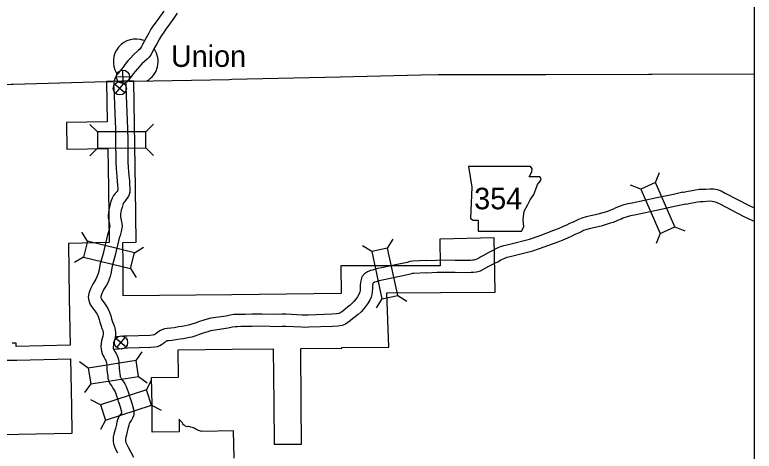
# Model space of a CAD drawing. Extents: x 1377389 to 1380723, y 1168351 to 1170484.
# Drawn here: x 1378097.6 to 1378279.2, y 1170112.1 to 1170219.2 of the extents above; entities that cross this region are included whole.
import ezdxf

# ---------------------------------------------------------------- set-up
doc = ezdxf.new("R2010")
doc.units = 0
doc.layers.add('B_Fill', color=7, linetype='Continuous')
doc.layers.add('B_Text', color=7, linetype='Continuous')

msp = doc.modelspace()

# ---------------------------------------------------------------- linework, layer by layer
at = {"layer": 'B_Fill'}
for p, q in [((1378124.19, 1170202.37), (1378124.12, 1170205.63)), ((1378122.53, 1170203.96), (1378125.78, 1170204.04)), ((1378122.16, 1170202.18), (1378124.65, 1170200.1)), ((1378122.36, 1170199.9), (1378124.45, 1170202.38)), ((1378117.9, 1170190.44), (1378116.03, 1170192.3)), ((1378129.78, 1170190.5), (1378131.64, 1170192.38)), ((1378117.93, 1170186.48), (1378116.07, 1170184.6)), ((1378129.81, 1170186.54), (1378131.68, 1170184.69)), ((1378254.91, 1170178), (1378255.87, 1170180.45)), ((1378251.28, 1170176.41), (1378248.82, 1170177.38)), ((1378259.67, 1170167.11), (1378262.12, 1170166.15)), ((1378115.43, 1170163.59), (1378114.06, 1170165.84)), ((1378256.04, 1170165.52), (1378255.07, 1170163.07)), ((1378185.24, 1170161.09), (1378183.02, 1170162.52)), ((1378189.11, 1170161.93), (1378190.54, 1170164.15)), ((1378126.97, 1170160.77), (1378129.23, 1170162.14)), ((1378114.49, 1170159.74), (1378112.23, 1170158.37)), ((1378126.03, 1170156.92), (1378127.4, 1170154.67)), ((1378191.63, 1170150.32), (1378193.85, 1170148.89)), ((1378187.76, 1170149.48), (1378186.33, 1170147.26)), ((1378122.45, 1170139.81), (1378124.94, 1170137.72)), ((1378122.65, 1170137.52), (1378124.74, 1170140.01)), ((1378127.37, 1170134.34), (1378128.92, 1170136.47)), ((1378115.63, 1170132.48), (1378113.5, 1170134.03)), ((1378127.99, 1170130.43), (1378130.12, 1170128.87)), ((1378116.25, 1170128.57), (1378114.7, 1170126.44)), ((1378129.94, 1170127.13), (1378131.15, 1170129.48)), ((1378118.64, 1170123.48), (1378116.29, 1170124.68)), ((1378131.16, 1170123.36), (1378133.51, 1170122.15)), ((1378119.85, 1170119.71), (1378118.65, 1170117.36))]:
    msp.add_line(p, q, dxfattribs=at)
for points in [[(1378134.21, 1170220.13), (1378133.13, 1170218.64), (1378132.29, 1170217.44), (1378131.53, 1170216.4), (1378131.05, 1170215.66), (1378130.54, 1170214.73), (1378129.86, 1170213.53), (1378129.38, 1170212.65), (1378128.99, 1170211.93), (1378128.72, 1170211.44), (1378128.46, 1170211), (1378128.27, 1170210.75), (1378128.01, 1170210.48), (1378126.68, 1170209.28), (1378126, 1170208.55), (1378125.36, 1170207.86), (1378124.74, 1170207.1), (1378124.36, 1170206.55), (1378123.87, 1170205.95), (1378123.4, 1170205.39), (1378123.08, 1170204.96), (1378122.87, 1170204.7), (1378122.67, 1170204.43), (1378122.49, 1170204.12), (1378122.38, 1170203.93), (1378122.21, 1170203.61), (1378122.07, 1170203.17), (1378121.96, 1170202.78), (1378121.94, 1170202.59)], [(1378137.51, 1170219.64), (1378136.66, 1170218.4), (1378135.58, 1170216.91), (1378134.73, 1170215.69), (1378134, 1170214.69), (1378133.63, 1170214.12), (1378133.16, 1170213.27), (1378132.48, 1170212.07), (1378132.02, 1170211.22), (1378131.62, 1170210.48), (1378131.31, 1170209.93), (1378130.97, 1170209.37), (1378130.58, 1170208.81), (1378130.08, 1170208.31), (1378128.78, 1170207.14), (1378128.2, 1170206.52), (1378127.63, 1170205.89), (1378127.13, 1170205.29), (1378126.76, 1170204.75), (1378126.18, 1170204.04), (1378125.75, 1170203.52), (1378125.47, 1170203.15), (1378125.26, 1170202.88), (1378125.16, 1170202.74), (1378125.09, 1170202.64), (1378125.09, 1170202.62)], [(1378125.72, 1170202.86), (1378126.88, 1170202.9), (1378150.29, 1170203.33), (1378150.89, 1170203.36), (1378177.46, 1170203.97), (1378197.29, 1170204.47)], [(1378197.29, 1170204.47), (1378201.57, 1170204.57), (1378227.75, 1170204.54), (1378227.98, 1170204.54), (1378253.31, 1170204.65), (1378254.09, 1170204.64), (1378279.16, 1170204.69)], [(1378012.99, 1170201.33), (1378018.47, 1170201.38), (1378044.97, 1170201.67), (1378045.21, 1170201.7), (1378070.3, 1170201.77), (1378070.43, 1170201.77), (1378096.77, 1170202.14), (1378097.18, 1170202.17), (1378120.12, 1170202.8), (1378121.69, 1170202.81)], [(1378124.12, 1170163.34), (1378127.44, 1170163.42), (1378127.27, 1170176.68), (1378126.83, 1170202.91), (1378123.92, 1170202.91), (1378120.13, 1170202.83), (1378120.3, 1170192.96), (1378110.28, 1170192.74), (1378110.4, 1170186.21)], [(1378122.09, 1170203.22), (1378122.07, 1170203.17), (1378121.96, 1170202.78), (1378121.9, 1170202.27), (1378121.86, 1170201.76), (1378121.89, 1170201.21), (1378122.31, 1170191.15)], [(1378124.95, 1170202.32), (1378124.94, 1170202.3), (1378124.91, 1170202.18), (1378124.89, 1170201.98), (1378124.87, 1170201.72), (1378124.88, 1170201.34), (1378125.31, 1170191.19)], [(1378122.31, 1170191.15), (1378122.35, 1170188.48), (1378122.38, 1170183.02), (1378122.49, 1170181.48), (1378122.63, 1170179.53), (1378122.75, 1170178.24), (1378122.81, 1170177.35), (1378122.87, 1170176.57), (1378122.89, 1170176.17), (1378122.88, 1170176.16), (1378122.86, 1170176.07), (1378122.83, 1170175.98), (1378122.8, 1170175.94), (1378122.58, 1170175.67), (1378122.25, 1170175.29), (1378121.88, 1170174.8), (1378121.51, 1170174.18), (1378121.23, 1170173.39), (1378121.05, 1170172.68), (1378120.85, 1170172.04), (1378120.66, 1170171.34), (1378120.58, 1170170.63), (1378120.54, 1170169.99), (1378120.57, 1170169.28), (1378120.68, 1170168.61), (1378120.78, 1170168.19), (1378120.84, 1170167.86), (1378120.9, 1170167.57), (1378120.93, 1170167.34), (1378120.81, 1170166.65), (1378120.62, 1170165.89), (1378120.38, 1170165.15), (1378119.28, 1170160.64), (1378118.74, 1170158.63)], [(1378125.31, 1170191.19), (1378125.35, 1170188.51), (1378125.38, 1170183.14), (1378125.48, 1170181.7), (1378125.62, 1170179.77), (1378125.74, 1170178.48), (1378125.8, 1170177.57), (1378125.86, 1170176.75), (1378125.89, 1170176.11), (1378125.85, 1170175.58), (1378125.7, 1170175.12), (1378125.53, 1170174.64), (1378125.23, 1170174.18), (1378124.89, 1170173.75), (1378124.59, 1170173.4), (1378124.36, 1170173.11), (1378124.24, 1170172.9), (1378124.1, 1170172.51), (1378123.94, 1170171.87), (1378123.74, 1170171.22), (1378123.62, 1170170.77), (1378123.57, 1170170.37), (1378123.55, 1170169.97), (1378123.56, 1170169.58), (1378123.62, 1170169.21), (1378123.72, 1170168.82), (1378123.8, 1170168.4), (1378123.86, 1170168.03), (1378123.96, 1170167.29), (1378123.75, 1170166.03), (1378123.5, 1170165.05), (1378123.26, 1170164.33), (1378122.18, 1170159.9), (1378121.63, 1170157.85)], [(1378110.4, 1170186.21), (1378120.42, 1170186.38), (1378120.6, 1170176.53), (1378120.77, 1170163.27), (1378110.77, 1170163.07), (1378110.96, 1170149.75), (1378111.21, 1170138.08), (1378097.98, 1170137.75)], [(1378261.6, 1170175.64), (1378259.35, 1170175.12), (1378255.28, 1170174.29)], [(1378261.6, 1170175.64), (1378261.77, 1170175.68), (1378262.92, 1170175.9), (1378263.92, 1170176.1), (1378264.77, 1170176.24), (1378265.64, 1170176.37), (1378266.54, 1170176.39), (1378267.28, 1170176.43), (1378268.26, 1170176.5), (1378269.23, 1170176.48), (1378270.08, 1170176.29), (1378271.02, 1170175.95), (1378272.05, 1170175.44), (1378277.95, 1170172.4), (1378279.16, 1170171.81)], [(1378255.23, 1170174.28), (1378249.19, 1170172.93), (1378248.19, 1170172.77), (1378247.11, 1170172.52), (1378245.72, 1170172.04), (1378244.85, 1170171.63)], [(1378262.4, 1170172.74), (1378263.5, 1170172.96), (1378264.45, 1170173.15), (1378265.23, 1170173.27), (1378265.91, 1170173.38), (1378266.65, 1170173.39), (1378267.45, 1170173.43), (1378268.34, 1170173.49), (1378268.87, 1170173.48), (1378269.25, 1170173.4), (1378269.85, 1170173.19), (1378270.69, 1170172.77), (1378276.61, 1170169.72), (1378278.73, 1170168.69), (1378279.16, 1170168.5)], [(1378198.58, 1170158.86), (1378201.17, 1170158.99), (1378202.14, 1170159.02), (1378205.73, 1170158.98), (1378208.55, 1170158.94), (1378209.53, 1170159), (1378210.04, 1170159.01), (1378210.38, 1170159.05), (1378210.87, 1170159.19), (1378211.26, 1170159.38), (1378211.81, 1170159.7), (1378212.62, 1170160.15), (1378213.33, 1170160.51), (1378214.11, 1170160.91), (1378214.9, 1170161.3), (1378215.49, 1170161.66), (1378216.1, 1170161.97), (1378216.88, 1170162.28), (1378217.68, 1170162.57), (1378218.84, 1170162.85), (1378223.98, 1170164.15), (1378226.58, 1170165.03), (1378229.97, 1170166.31), (1378231.13, 1170166.75), (1378232.18, 1170167.19), (1378233.19, 1170167.63), (1378233.91, 1170168.01), (1378234.78, 1170168.41), (1378235.41, 1170168.71), (1378236.06, 1170169.04), (1378236.92, 1170169.37), (1378237.95, 1170169.66), (1378238.98, 1170169.89), (1378240.18, 1170170.2), (1378241.21, 1170170.4), (1378242.03, 1170170.64), (1378242.97, 1170170.95), (1378243.61, 1170171.15), (1378244.4, 1170171.46), (1378244.85, 1170171.63)], [(1378262.4, 1170172.74), (1378260, 1170172.2), (1378255.88, 1170171.35)], [(1378255.89, 1170171.35), (1378249.76, 1170169.98), (1378248.77, 1170169.83), (1378247.94, 1170169.63), (1378246.91, 1170169.28), (1378246.88, 1170169.26)], [(1378198.74, 1170155.86), (1378201.28, 1170156), (1378202.17, 1170156.02), (1378205.7, 1170155.98), (1378208.62, 1170155.94), (1378209.67, 1170156), (1378210.26, 1170156.02), (1378210.96, 1170156.1), (1378211.94, 1170156.38), (1378212.67, 1170156.73), (1378213.29, 1170157.09), (1378214.02, 1170157.5), (1378214.69, 1170157.84), (1378215.46, 1170158.23), (1378216.34, 1170158.67), (1378216.95, 1170159.03), (1378217.35, 1170159.24), (1378217.94, 1170159.48), (1378218.54, 1170159.69), (1378219.57, 1170159.94), (1378224.83, 1170161.27), (1378227.59, 1170162.21), (1378231.04, 1170163.5), (1378232.24, 1170163.97), (1378233.36, 1170164.43), (1378234.48, 1170164.93), (1378235.22, 1170165.31), (1378236.06, 1170165.69), (1378236.74, 1170166.02), (1378237.28, 1170166.29), (1378237.87, 1170166.52), (1378238.69, 1170166.75), (1378239.68, 1170166.98), (1378240.84, 1170167.27), (1378241.91, 1170167.48), (1378242.92, 1170167.77), (1378243.89, 1170168.09), (1378244.61, 1170168.32), (1378245.5, 1170168.67), (1378246.88, 1170169.26), (1378246.54, 1170169.07)], [(1378202.15, 1170150.99), (1378215.57, 1170151.1), (1378215.27, 1170164.42), (1378201.96, 1170164.15), (1378202.06, 1170157.57)], [(1378124.23, 1170150.17), (1378124.2, 1170158.05), (1378124.12, 1170163.34)], [(1378118.74, 1170158.63), (1378118.61, 1170158.16), (1378118.22, 1170156.29), (1378118.09, 1170155.73), (1378117.95, 1170155.28), (1378117.77, 1170154.84), (1378117.5, 1170154.31), (1378117.23, 1170153.89), (1378116.88, 1170153.26), (1378116.53, 1170152.59), (1378116.22, 1170151.95), (1378115.98, 1170151.31), (1378115.8, 1170150.77), (1378115.66, 1170149.91), (1378115.82, 1170149.08), (1378116.07, 1170148.28), (1378116.48, 1170147.55), (1378116.89, 1170147.01), (1378117.27, 1170146.51), (1378117.58, 1170146.06), (1378117.81, 1170145.7), (1378118.05, 1170145.13), (1378118.29, 1170144.43), (1378118.48, 1170143.72), (1378118.78, 1170142.79), (1378119.01, 1170142.22), (1378119.19, 1170141.71), (1378119.29, 1170141.31), (1378119.33, 1170141.06), (1378119.32, 1170140.81)], [(1378121.63, 1170157.85), (1378121.53, 1170157.46), (1378121.15, 1170155.64), (1378120.99, 1170154.96), (1378120.79, 1170154.29), (1378120.5, 1170153.58), (1378120.1, 1170152.81), (1378119.81, 1170152.35), (1378119.51, 1170151.82), (1378119.21, 1170151.25), (1378118.98, 1170150.78), (1378118.81, 1170150.31), (1378118.73, 1170150.06), (1378118.71, 1170149.95), (1378118.74, 1170149.8), (1378118.84, 1170149.49), (1378119, 1170149.19), (1378119.28, 1170148.81), (1378119.69, 1170148.28), (1378120.08, 1170147.73), (1378120.49, 1170147.09), (1378120.85, 1170146.2), (1378121.16, 1170145.32), (1378121.36, 1170144.57), (1378121.61, 1170143.81), (1378121.82, 1170143.27), (1378122.06, 1170142.59), (1378122.23, 1170141.93), (1378122.34, 1170141.23), (1378122.32, 1170140.69)], [(1378202.06, 1170157.57), (1378177.69, 1170157.59), (1378177.76, 1170150.78), (1378150.86, 1170150.49), (1378124.23, 1170150.17)], [(1378191.49, 1170157.91), (1378188.04, 1170157.16), (1378186.31, 1170156.8), (1378185.46, 1170156.54), (1378184.96, 1170156.39)], [(1378198.6, 1170158.86), (1378195.31, 1170158.72), (1378194.59, 1170158.66), (1378193.93, 1170158.43), (1378191.49, 1170157.91)], [(1378184.96, 1170156.39), (1378184.82, 1170156.35), (1378184.22, 1170156.1), (1378183.49, 1170155.64), (1378182.85, 1170154.85), (1378182.59, 1170153.88), (1378182.44, 1170152.88), (1378182.44, 1170152.1), (1378182.4, 1170151.51), (1378182.36, 1170151.21), (1378182.27, 1170150.91), (1378182.11, 1170150.54), (1378181.76, 1170149.99), (1378181.32, 1170149.43), (1378180.85, 1170148.83), (1378180.48, 1170148.38), (1378179.97, 1170147.95), (1378179.31, 1170147.41), (1378178.72, 1170146.93), (1378178.12, 1170146.45), (1378177.69, 1170146.12), (1378177.43, 1170145.96), (1378177.17, 1170145.85), (1378176.59, 1170145.77), (1378175.47, 1170145.7), (1378169.71, 1170145.5), (1378168.83, 1170145.45), (1378168.17, 1170145.49), (1378164.25, 1170145.68), (1378163.23, 1170145.67), (1378162.15, 1170145.64), (1378158.33, 1170145.74), (1378155.87, 1170145.69), (1378154.2, 1170145.65), (1378153.06, 1170145.65), (1378152.12, 1170145.64), (1378151.38, 1170145.6), (1378150.48, 1170145.44), (1378149.5, 1170145.25), (1378145.71, 1170144.69), (1378144.88, 1170144.52), (1378144.06, 1170144.25), (1378142.92, 1170143.89), (1378141.88, 1170143.53), (1378141.11, 1170143.25), (1378140.28, 1170142.98), (1378139.51, 1170142.81), (1378138.63, 1170142.65), (1378137.82, 1170142.56), (1378136.7, 1170142.36), (1378135.92, 1170142.26), (1378135.01, 1170142.18), (1378134.37, 1170142.11), (1378133.69, 1170141.86), (1378133.19, 1170141.59), (1378132.64, 1170141.2), (1378132.33, 1170140.93), (1378132.07, 1170140.76), (1378131.92, 1170140.67), (1378131.78, 1170140.62), (1378131.45, 1170140.56), (1378130.8, 1170140.5), (1378125.17, 1170140.33), (1378124.26, 1170140.29), (1378122.7, 1170140.14), (1378122.24, 1170140.07)], [(1378198.73, 1170155.86), (1378195.5, 1170155.73), (1378195.21, 1170155.7), (1378194.73, 1170155.54), (1378192.12, 1170154.97)], [(1378185.85, 1170153.53), (1378185.84, 1170153.52), (1378185.6, 1170153.43), (1378185.57, 1170153.41), (1378185.53, 1170153.27), (1378185.44, 1170152.65), (1378185.44, 1170152), (1378185.39, 1170151.2), (1378185.3, 1170150.57), (1378185.1, 1170149.9), (1378184.77, 1170149.13), (1378184.22, 1170148.26), (1378183.68, 1170147.58), (1378183.19, 1170146.95), (1378182.63, 1170146.26), (1378181.88, 1170145.63), (1378181.19, 1170145.08), (1378180.61, 1170144.61), (1378179.98, 1170144.1), (1378179.39, 1170143.64), (1378178.77, 1170143.26), (1378177.96, 1170142.94), (1378176.91, 1170142.78), (1378175.62, 1170142.7), (1378169.84, 1170142.5), (1378168.81, 1170142.44), (1378167.99, 1170142.5), (1378164.2, 1170142.68), (1378163.28, 1170142.67), (1378162.15, 1170142.64), (1378158.32, 1170142.74), (1378155.93, 1170142.69), (1378154.24, 1170142.65), (1378153.08, 1170142.65), (1378152.22, 1170142.64), (1378151.72, 1170142.62), (1378151.03, 1170142.49), (1378150, 1170142.3), (1378146.24, 1170141.73), (1378145.64, 1170141.61), (1378144.97, 1170141.4), (1378143.87, 1170141.05), (1378142.88, 1170140.7), (1378142.09, 1170140.41), (1378141.07, 1170140.08), (1378140.1, 1170139.87), (1378139.06, 1170139.68), (1378138.24, 1170139.59), (1378137.15, 1170139.4), (1378136.25, 1170139.28), (1378135.31, 1170139.19), (1378135.06, 1170139.16), (1378134.91, 1170139.11), (1378134.77, 1170139.04), (1378134.51, 1170138.85), (1378134.14, 1170138.53), (1378133.63, 1170138.19), (1378133.19, 1170137.95), (1378132.57, 1170137.72), (1378131.87, 1170137.59), (1378131, 1170137.5), (1378125.29, 1170137.33), (1378124.48, 1170137.29), (1378123.04, 1170137.15), (1378121.9, 1170137.01)], [(1378192.12, 1170154.97), (1378188.66, 1170154.22), (1378187.05, 1170153.89), (1378186.33, 1170153.68), (1378185.85, 1170153.53)], [(1378151.44, 1170110.32), (1378151.3, 1170117.04), (1378143.55, 1170116.92), (1378143.02, 1170117.05), (1378142.49, 1170117.23), (1378142.22, 1170117.37), (1378141.9, 1170117.6), (1378141.66, 1170117.73), (1378141.46, 1170117.8), (1378141.19, 1170117.91), (1378140.87, 1170117.99), (1378140.61, 1170118.05), (1378140.29, 1170118.1), (1378140.1, 1170118.11), (1378139.82, 1170118.07), (1378139.59, 1170118.15), (1378139.34, 1170118.34), (1378139.07, 1170118.57), (1378138.87, 1170118.81), (1378138.68, 1170119.12), (1378138.5, 1170119.3), (1378138.25, 1170119.64), (1378137.96, 1170119.92), (1378137.99, 1170116.83), (1378131.37, 1170116.72), (1378131.31, 1170123.47), (1378131.2, 1170130.15), (1378137.83, 1170130.25), (1378137.74, 1170136.93), (1378151.01, 1170137.13), (1378161.08, 1170137.2), (1378161.22, 1170123.81), (1378161.32, 1170113.76), (1378167.99, 1170113.81), (1378167.93, 1170123.84), (1378167.8, 1170137.26), (1378177.87, 1170137.34), (1378177.87, 1170137.54), (1378189.43, 1170137.6), (1378188.94, 1170150.94), (1378202.15, 1170150.99)], [(1378119.32, 1170140.81), (1378119.22, 1170140.3), (1378119.05, 1170139.71), (1378118.93, 1170139.24), (1378118.85, 1170138.53), (1378118.74, 1170137.78), (1378118.8, 1170137.08), (1378118.87, 1170136.62), (1378119.03, 1170136.06), (1378119.29, 1170135.52), (1378119.53, 1170135.07), (1378119.81, 1170134.61), (1378119.99, 1170134.3), (1378120.07, 1170134.07), (1378120.14, 1170133.68), (1378120.18, 1170133.18), (1378120.21, 1170132.69), (1378120.23, 1170132.12), (1378120.31, 1170131.37), (1378120.44, 1170130.55), (1378120.49, 1170130), (1378120.68, 1170129.25), (1378121.05, 1170128.55), (1378121.41, 1170128.05), (1378121.7, 1170127.56), (1378122.02, 1170127.06), (1378122.24, 1170126.67), (1378122.4, 1170126.27), (1378122.59, 1170125.68), (1378122.83, 1170124.97), (1378123.03, 1170124.33), (1378123.15, 1170123.95), (1378123.47, 1170122.97), (1378123.79, 1170121.76), (1378123.83, 1170121.53), (1378123.83, 1170121.5), (1378123.78, 1170121.4), (1378123.49, 1170121.03)], [(1378122.32, 1170140.69), (1378122.31, 1170140.47), (1378122.14, 1170139.59), (1378121.95, 1170138.91), (1378121.88, 1170138.68), (1378121.82, 1170138.14), (1378121.76, 1170137.7), (1378121.78, 1170137.44), (1378121.8, 1170137.26), (1378121.84, 1170137.15), (1378121.97, 1170136.87), (1378122.14, 1170136.55), (1378122.39, 1170136.14), (1378122.72, 1170135.56), (1378122.98, 1170134.85), (1378123.12, 1170134.05), (1378123.17, 1170133.39), (1378123.2, 1170132.84), (1378123.22, 1170132.33), (1378123.28, 1170131.76), (1378123.41, 1170130.94), (1378123.45, 1170130.53), (1378123.51, 1170130.32), (1378123.61, 1170130.13), (1378123.92, 1170129.69), (1378124.26, 1170129.13), (1378124.6, 1170128.59), (1378124.95, 1170127.95), (1378125.22, 1170127.29), (1378125.44, 1170126.62), (1378125.67, 1170125.91), (1378125.89, 1170125.24), (1378126.01, 1170124.85), (1378126.35, 1170123.82), (1378126.73, 1170122.4), (1378126.81, 1170121.92), (1378126.85, 1170121.45), (1378126.84, 1170121.12), (1378126.78, 1170120.74), (1378126.52, 1170120.14), (1378126.25, 1170119.7), (1378126.2, 1170119.63), (1378125.98, 1170119.36)], [(1378097.98, 1170137.75), (1378097.96, 1170138.58), (1378096.99, 1170138.57)], [(1378094.77, 1170134.38), (1378098.07, 1170134.42), (1378111.28, 1170134.74), (1378111.52, 1170123.07), (1378111.59, 1170116.38), (1378098.49, 1170116.15), (1378085.23, 1170116)], [(1378123.49, 1170121.03), (1378123.17, 1170120.56), (1378122.85, 1170119.77), (1378122.69, 1170119.16), (1378122.47, 1170118.28), (1378122.31, 1170117.64), (1378122.12, 1170116.86), (1378121.96, 1170116.29), (1378121.8, 1170115.62), (1378121.76, 1170115.03), (1378121.76, 1170114.48), (1378121.88, 1170113.84), (1378122.06, 1170113.24), (1378122.31, 1170112.59), (1378122.84, 1170111.64)], [(1378125.98, 1170119.36), (1378125.83, 1170119.13), (1378125.7, 1170118.82), (1378125.6, 1170118.43), (1378125.38, 1170117.54), (1378125.22, 1170116.91), (1378125.03, 1170116.11), (1378124.87, 1170115.54), (1378124.78, 1170115.15), (1378124.76, 1170114.92), (1378124.76, 1170114.75), (1378124.8, 1170114.55), (1378124.9, 1170114.22), (1378125.03, 1170113.87), (1378125.48, 1170113.07), (1378126.78, 1170110.59)]]:
    msp.add_lwpolyline(points, dxfattribs=at)
for points in [[(1378117.93, 1170186.48), (1378129.81, 1170186.54), (1378129.78, 1170190.5), (1378117.9, 1170190.44)], [(1378209.04, 1170181.98), (1378209.8, 1170176.91), (1378209.46, 1170169.21), (1378210.14, 1170168.79), (1378211.4, 1170168.79), (1378211.4, 1170166.08), (1378222.06, 1170166.08), (1378222.57, 1170167.18), (1378222.4, 1170168.96), (1378222.65, 1170170.99), (1378223.58, 1170172.59), (1378224.18, 1170173.78), (1378225.02, 1170175.05), (1378225.53, 1170176.4), (1378225.95, 1170177.5), (1378226.71, 1170178.43), (1378226.88, 1170179.02), (1378226.55, 1170179.45), (1378223.92, 1170179.45), (1378224.52, 1170180.63), (1378224.6, 1170181.39), (1378224.25, 1170181.98)], [(1378251.28, 1170176.41), (1378256.04, 1170165.52), (1378259.67, 1170167.11), (1378254.91, 1170178)], [(1378126.97, 1170160.77), (1378115.43, 1170163.59), (1378114.49, 1170159.74), (1378126.03, 1170156.92)], [(1378191.63, 1170150.32), (1378189.11, 1170161.93), (1378185.24, 1170161.09), (1378187.76, 1170149.48)], [(1378116.25, 1170128.57), (1378127.99, 1170130.43), (1378127.37, 1170134.34), (1378115.63, 1170132.48)], [(1378129.94, 1170127.13), (1378118.64, 1170123.48), (1378119.85, 1170119.71), (1378131.16, 1170123.36)]]:
    msp.add_lwpolyline(points, close=True, dxfattribs=at)
for centre, radius in [((1378124.16, 1170204), 1.63), ((1378123.4, 1170201.14), 1.62), ((1378123.7, 1170138.77), 1.62)]:
    msp.add_circle(centre, radius, dxfattribs=at)
for start, end in [(69.1456, 210.9637), (299.8989, 33.6901)]:
    msp.add_arc((1378127.31, 1170207.72), 5.5, start, end, dxfattribs=at)
at = {"layer": 'B_Text'}
msp.add_lwpolyline([(1377549.76, 1170388.77), (1378279.16, 1170388.77), (1378279.16, 1169604.28), (1377549.76, 1169604.28)], close=True, dxfattribs=at)

# ---------------------------------------------------------------- texts
at = {"layer": 'B_Fill'}
for s, p in [('Union', (1378135.95, 1170206.41)), ('354', (1378210.4, 1170171.46))]:
    msp.add_text(s, height=5.28, dxfattribs=at).set_placement(p)

doc.saveas('drawing.dxf')
